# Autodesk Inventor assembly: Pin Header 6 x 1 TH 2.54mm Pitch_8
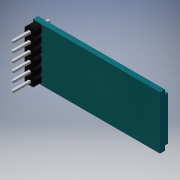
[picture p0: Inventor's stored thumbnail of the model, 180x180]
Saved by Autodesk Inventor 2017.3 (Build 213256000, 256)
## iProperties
Part Number: Pin Header 6 x 1 TH 2.54mm Pitch_8
Material: Générique
Document SubType Name: Modeling
Designer: ficho
Density: 1 g/cm^3
Appearance: Par défaut
Author: ficho
Revision Number: NONE
Part Number: Pin Header 6 x 1 TH 2.54mm Pitch_11
Part Number: Pin Header 6 x 1 TH 2.54mm Pitch_9
Part Number: Pin Header 6 x 1 TH 2.54mm Pitch_6
Part Number: Pin Header 6 x 1 TH 2.54mm Pitch_5
Part Number: Pin Header 6 x 1 TH 2.54mm Pitch
Part Number: Assembly1
Document SubType Name: Assembly
Part Number: Pin Header 6 x 1 TH 2.54mm Pitch_1
Part Number: Pin Header 6 x 1 TH 2.54mm Pitch_7
Part Number: _______-________9
Created: 2017-09
Part Number: HC-SERIES
Description: STEP AP214
Title: HC-SERIES.stp
Preprocessor: Spatial InterOp 3D
Part Number: Assembly8
Part Number: Pin Header 6 x 1 TH 2.54mm Pitch_3
Part Number: Pin Header 6 x 1 TH 2.54mm Pitch_2
Part Number: Pin Header 6 x 1 TH 2.54mm Pitch_4
Part Number: Pin Header 6 x 1 TH 2.54mm Pitch_10
Part Number: module bluetooth HC05
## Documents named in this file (18)
- **C:\Users\ficho\Desktop\réforme\activité rentrée\module bluetooth HC05.iam*LocalDocs*xSyrrlxdeAo2we5o33irwgv2hKa*Pin Header 6 x 1 TH 2.54mm Pitch_8.ipt
- **C:\Users\ficho\Desktop\réforme\activité rentrée\module bluetooth HC05.iam*LocalDocs*xIqa0mbpj2kpeu2s3Vow1hgjwBe*Pin Header 6 x 1 TH 2.54mm Pitch_11.ipt
- **C:\Users\ficho\Desktop\réforme\activité rentrée\module bluetooth HC05.iam*LocalDocs*x23qhu22oFhchuown25svkjugEb*Pin Header 6 x 1 TH 2.54mm Pitch_9.ipt
- **C:\Users\ficho\Desktop\réforme\activité rentrée\module bluetooth HC05.iam*LocalDocs*x0ojpfl5tM4hieu44G0xylw53Za*Pin Header 6 x 1 TH 2.54mm Pitch_6.ipt
- **C:\Users\ficho\Desktop\réforme\activité rentrée\module bluetooth HC05.iam*LocalDocs*xF1pksyqp5slbu3srJpcxh42gJg*Pin Header 6 x 1 TH 2.54mm Pitch_5.ipt
- **C:\Users\ficho\Desktop\réforme\activité rentrée\module bluetooth HC05.iam*LocalDocs*x5zjtt0al5yh0ee0nGwaqhxvcYc*Pin Header 6 x 1 TH 2.54mm Pitch.ipt
- **C:\Users\ficho\Desktop\réforme\activité rentrée\module bluetooth HC05.iam*LocalDocs*xG2tbp0i2Ndthuoou2tv2kdtx1f*Assembly1.iam
- **C:\Users\ficho\Desktop\réforme\activité rentrée\module bluetooth HC05.iam*LocalDocs*xJzlmsbvxK3nnu4keVhnqvstaWc*_______-________9.ipt
- **C:\Users\ficho\Desktop\réforme\activité rentrée\module bluetooth HC05.iam*LocalDocs*xRvdl5vemVbc4uwk5I0e5krrdRc*Pin Header 6 x 1 TH 2.54mm Pitch_1.ipt
- **C:\Users\ficho\Desktop\réforme\activité rentrée\module bluetooth HC05.iam*LocalDocs*xLmo1xzbnPpolevcfNyrb01ljXc*Pin Header 6 x 1 TH 2.54mm Pitch_7.ipt
- **C:\Users\ficho\Desktop\réforme\activité rentrée\module bluetooth HC05.iam*LocalDocs*xLgaoidegSve4uck3YqqigxhkYc*HC-SERIES.iam
- **C:\Users\ficho\Desktop\réforme\activité rentrée\module bluetooth HC05.iam*LocalDocs*xRg1rza3sB0leefol5oalrhojSb*Assembly8.iam
- **C:\Users\ficho\Desktop\réforme\activité rentrée\module bluetooth HC05.iam*LocalDocs*xW1banqnr5l45etgd3hjegmt0Rg*Pin Header 6 x 1 TH 2.54mm Pitch_2.ipt
- **C:\Users\ficho\Desktop\réforme\activité rentrée\module bluetooth HC05.iam*LocalDocs*xSgh3qnv3WoqvuqgzTb3mbswwLb*Pin Header 6 x 1 TH 2.54mm Pitch_3.ipt
- **C:\Users\ficho\Desktop\réforme\activité rentrée\module bluetooth HC05.iam*LocalDocs*xVq2az4ju5u24ub4oOmqj2p3f0c*Pin Header 6 x 1 TH 2.54mm Pitch_4.ipt
- **C:\Users\ficho\Desktop\réforme\activité rentrée\module bluetooth HC05.iam*LocalDocs*xWrkde54zSznfuds3Vua50qqeKf*Pin Header 6 x 1 TH 2.54mm Pitch_10.ipt
- C:\Users\ficho\Desktop\réforme\activité rentrée\module bluetooth HC05.iam
- C:\Users\ficho\Desktop\réforme\activité rentrée\HC-SERIES.stp
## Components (1 placed, 1 different names)
1. HC-SERIES:1 [sub-assembly]
